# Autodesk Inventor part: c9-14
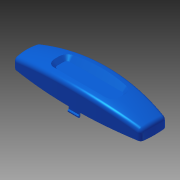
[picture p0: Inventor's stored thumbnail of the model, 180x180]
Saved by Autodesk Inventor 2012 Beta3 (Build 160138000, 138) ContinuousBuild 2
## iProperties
Created: 2011-01
Part Number: c9-14
Material: Default
Document SubType Name: Modeling
Designer: Beta-8540w
Density: 1 g/cm^3
Author: Beta-8540w
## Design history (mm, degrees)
derived "c9-13.ipt"
feature "Front::c9-13.ipt" dims "d0" = 10
tag "TaggingFeature1"
body "Solid1"
